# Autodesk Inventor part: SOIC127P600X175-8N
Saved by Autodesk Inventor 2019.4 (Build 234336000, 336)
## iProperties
Created: 2021-02
Part Number: SOIC127P600X175-8N
Material: Generic
Document SubType Name: Modeling
Designer: Administrator
Density: 1 g/cm^3
Appearance: Default
Title: SOIC127P600X175-8N
Author: Administrator
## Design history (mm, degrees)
feature "Body1"
body "Solid1"
